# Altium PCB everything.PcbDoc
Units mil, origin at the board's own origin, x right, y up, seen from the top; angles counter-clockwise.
Board outline 6000 x 4000 mil, 2 copper layers (Top Layer, Bottom Layer); 0 components, 0 nets, 0 pads, 0 vias.
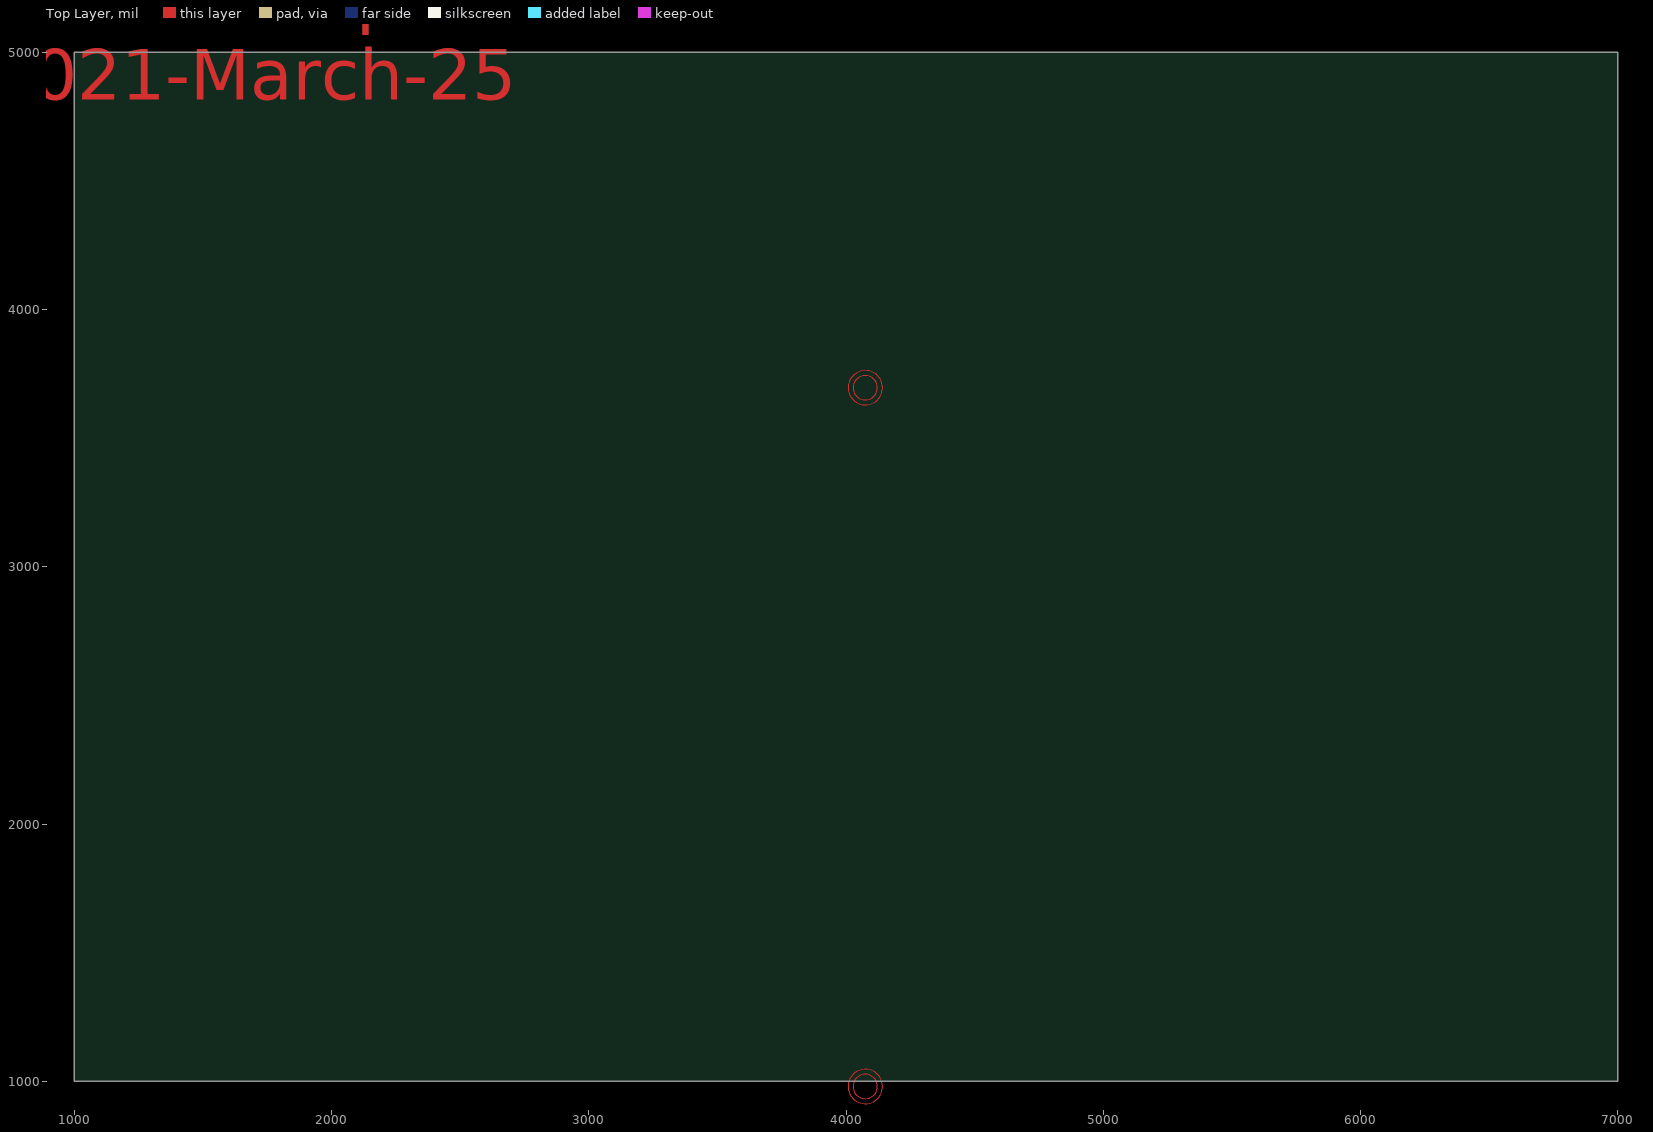
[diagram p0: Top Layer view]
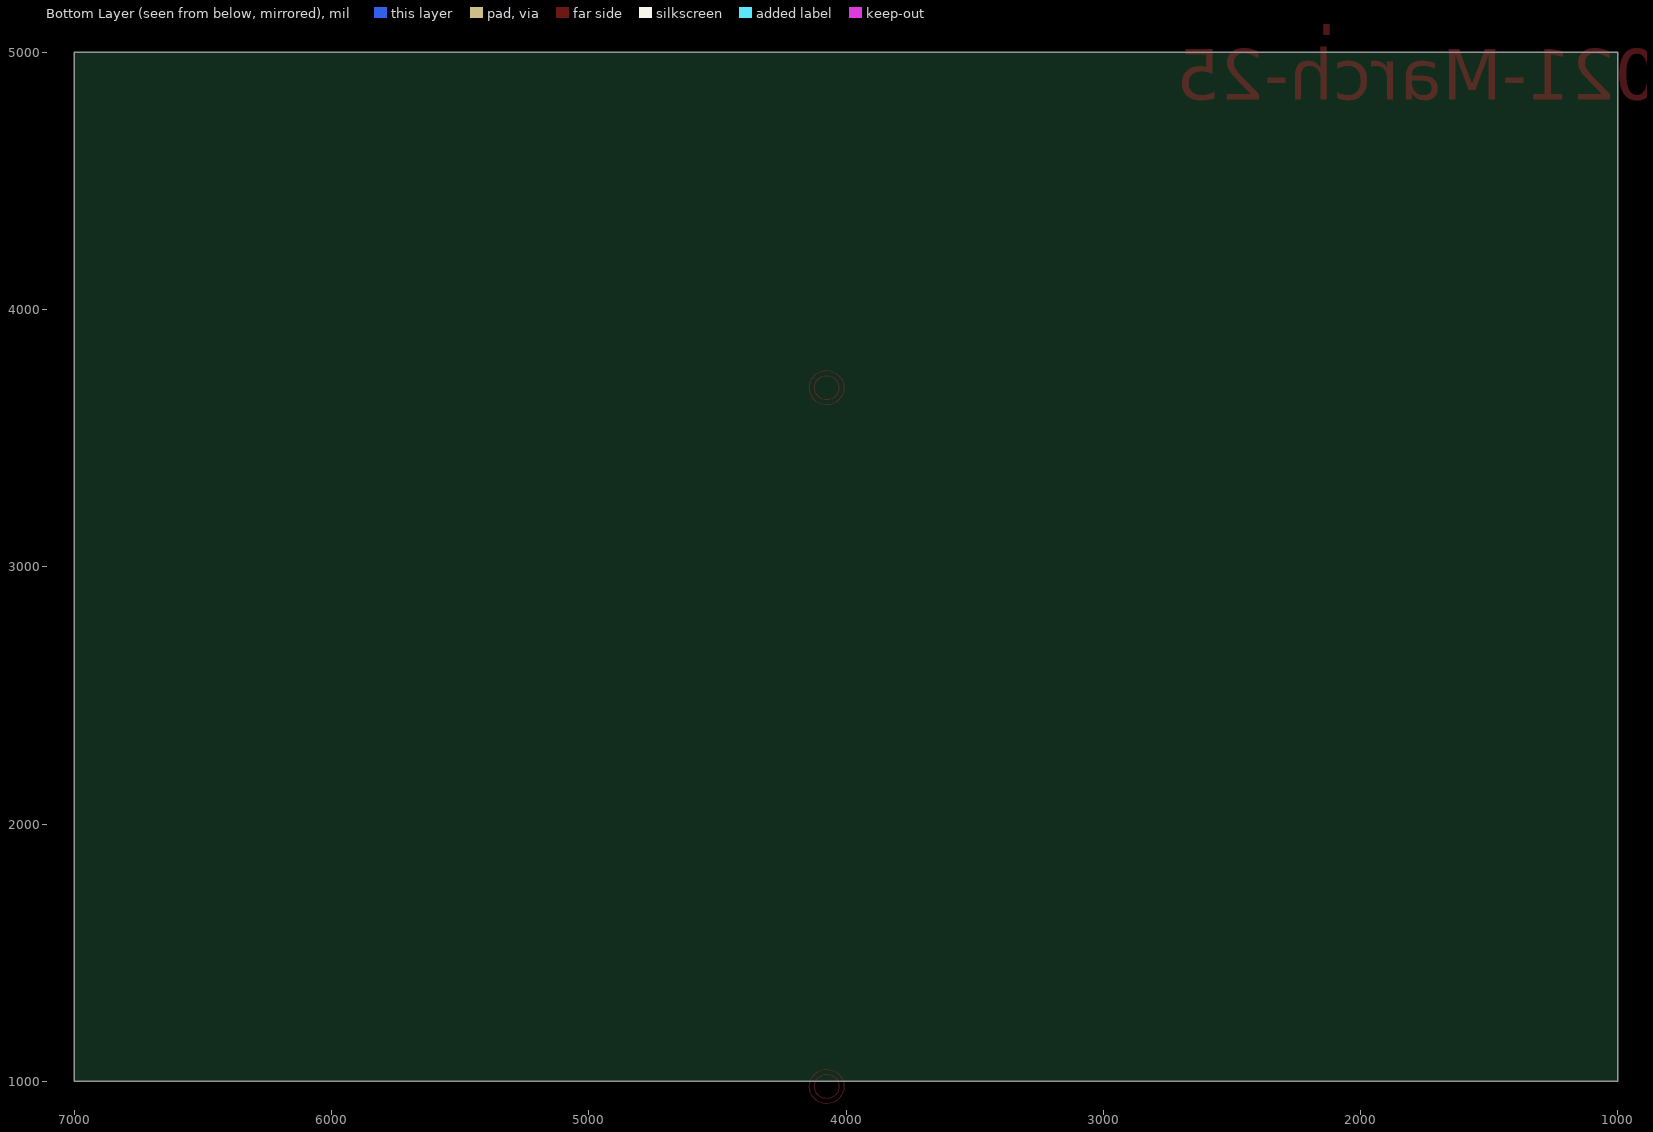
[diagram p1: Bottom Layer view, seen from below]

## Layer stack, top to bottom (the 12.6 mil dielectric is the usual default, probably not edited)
Top Solder: solder mask 0.4, Solder Resist, Dk 3.5
Top Layer: signal copper 1.4
Dielectric 1: dielectric 12.6, FR-4, Dk 4.8
Bottom Layer: signal copper 1.4
Bottom Solder: solder mask 0.4, Solder Resist, Dk 3.5

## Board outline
1000,1000 7000,1000 7000,5000 1000,5000

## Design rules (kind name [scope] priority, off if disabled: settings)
Clearance [All] p1: gap=10 ignorepadtopadclearanceinfootprint=FALSE except(0: Arc-Hole Track-Hole SMDPad-Hole THPad-Hole Via-Hole Fill-Hole Poly-Hole Region-Hole Text-Hole)
PolygonConnect [All] p1: connectstyle=Relief reliefconductorwidth=10 reliefentries=4 polygonreliefangle="90 Angle" airgapwidth=10
RoutingVias [All] p1: holewidth=28 width=50 viastyle="Through Hole" minholewidth=28 minwidth=50 maxholewidth=28 maxwidth=50
SolderMaskExpansion [All] p1: expansion=4 istentingtop=FALSE
Width [All] p1: maxlimit=10 minlimit=10 preferedwidth=10
30 further rules are at their usual default settings.

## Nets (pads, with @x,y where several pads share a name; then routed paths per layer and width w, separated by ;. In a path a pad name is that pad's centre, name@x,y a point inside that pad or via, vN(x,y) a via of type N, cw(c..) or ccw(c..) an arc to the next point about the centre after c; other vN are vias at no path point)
copper on no net: | length 46414.5
  Top Layer w0.5: 17253.01,7567.58 17253.01,7869.71 ; 17253.01,14476.48 17253.01,14778.6 ; 17351.43,7616.8 17941.98,7616.8 ; 17351.43,14525.69 17941.98,14525.69 ; 17573.21,7723.48 17589.66,7739.93 17622.43,7739.93 17638.88,7723.48 17638.88,7707.03 17622.43,7690.71 17589.66,7690.71 17573.21,7674.26 17573.21,7641.49 17638.88,7641.49 ; 17573.21,14632.37 17589.66,14648.83 17622.43,14648.83 17638.88,14632.37 17638.88,14615.92 17622.43,14599.6 17589.66,14599.6 17573.21,14583.15 17573.21,14550.38 17638.88,14550.38 ; 18040.41,7567.58 18040.41,7869.71 ; 18040.41,14476.48 18040.41,14778.6 ; 25456.33,7901.12 25456.33,8151.63 ; 25554.75,8102.42 25751.6,8102.42 ; 25596.22,8127.07 25628.97,8127.07 ; 25596.22,8209.05 25612.59,8225.51 25612.59,8127.07 ; 25850.03,7901.12 25850.03,8151.63 ; 26019.53,17666.21 26150.48,17666.21 ; 26019.53,18539.17 26085.01,18604.65 26215.95,18604.65 26281.42,18539.17 26281.42,18473.7 26215.95,18408.23 26085.01,18408.23 26019.53,18342.76 26019.53,18210.9 26281.42,18210.9 ; 26281.42,17468.88 26019.53,17468.88 26019.53,17862.62 26281.42,17862.62 ; 26675.17,17468.88 26609.7,17534.35 ; 26740.64,18539.17 26806.11,18604.65 26937.06,18604.65 27002.53,18539.17 27002.53,18473.7 26937.06,18408.23 26806.11,18408.23 26740.64,18342.76 26740.64,18210.9 27002.53,18210.9 ; 27068,17468.88 26871.59,17468.88 26806.11,17534.35 26806.11,17666.21 26871.59,17731.68 27068,17731.68 ; 27134.39,18210.9 27265.33,18210.9 ; 27134.39,18539.17 27199.86,18604.65 27199.86,18210.9 ; 27199.86,17468.88 27199.86,17862.62 ; 27199.86,17600.73 27330.8,17731.68 27396.28,17731.68 27461.75,17666.21 27461.75,17468.88 ; 27396.28,18408.23 27658.17,18408.23 ; 27790.02,18210.9 27790.02,18342.76 ; 27986.44,17468.88 28117.39,17468.88 ; 27986.44,17797.15 28051.91,17862.62 28051.91,17468.88 ; 28051.91,18210.9 28051.91,18342.76 ; 28182.86,18079.96 28182.86,18473.7 ; 28182.86,18210.9 28380.19,18210.9 28445.66,18276.37 28445.66,18408.23 28380.19,18473.7 28249.24,18473.7 28182.86,18408.23 ; 28576.6,17337.93 28576.6,17731.68 ; 28576.6,17468.88 28773.02,17468.88 28839.4,17534.35 28839.4,17666.21 28773.02,17731.68 28642.08,17731.68 28576.6,17666.21 ; 28576.6,18210.9 28576.6,18473.7 ; 28576.6,18342.76 28707.55,18473.7 28773.02,18473.7 28839.4,18408.23 ; 28970.35,18210.9 28970.35,18473.7 ; 28970.35,18539.17 28970.35,18604.65 ; 29101.29,18604.65 29101.29,18276.37 29166.77,18210.9 ; 29232.24,17468.88 29035.82,17468.88 28970.35,17534.35 28970.35,17666.21 29035.82,17731.68 29232.24,17731.68 ; 29297.71,18408.23 29560.51,18408.23 ; 29363.18,17468.88 29560.51,17468.88 29625.98,17534.35 29560.51,17600.73 29429.57,17600.73 29363.18,17666.21 29429.57,17731.68 29625.98,17731.68 ; 29691.46,18210.9 29822.4,18210.9 ; 29691.46,18539.17 29756.93,18604.65 29756.93,18210.9 ; 29953.35,18276.37 30019.73,18210.9 30150.67,18210.9 30216.15,18276.37 30216.15,18408.23 30150.67,18473.7 29953.35,18473.7 29953.35,18604.65 30216.15,18604.65 ; 26609.7,17534.35 26609.7,17666.21 26544.22,17731.68 26477.84,17731.68 26412.37,17666.21 26412.37,17534.35 26477.84,17468.88 26544.22,17468.88 26609.7,17534.35 ; 27790.02,18342.76 27920.97,18604.65 28051.91,18342.76 ; 27790.02,18342.76 28051.91,18342.76 ; 500.25,979.57 ccw(c453.01,979.57) 500.25,979.57 ; 500.25,7888.46 ccw(c453.01,7888.46) 500.25,7888.46 ; 500.25,10605 ccw(c453.01,10605) 500.25,10605 ; 519.93,979.57 ccw(c453.01,979.57) 519.93,979.57 ; 519.93,7888.46 ccw(c453.01,7888.46) 519.93,7888.46 ; 519.93,10605 ccw(c453.01,10605) 519.93,10605 ; 697.1,3696.11 ccw(c649.86,3696.11) 697.1,3696.11 ; 716.78,3696.11 ccw(c649.86,3696.11) 716.78,3696.11 ; 3925.45,10605 ccw(c3878.21,10605) 3925.45,10605 ; 3945.13,10605 ccw(c3878.21,10605) 3945.13,10605 ; 4122.3,979.57 ccw(c4075.06,979.57) 4122.3,979.57 ; 4122.3,3696.11 ccw(c4075.06,3696.11) 4122.3,3696.11 ; 4122.3,7888.46 ccw(c4075.06,7888.46) 4122.3,7888.46 ; 4141.98,979.57 ccw(c4075.06,979.57) 4141.98,979.57 ; 4141.98,3696.11 ccw(c4075.06,3696.11) 4141.98,3696.11 ; 4141.98,7888.46 ccw(c4075.06,7888.46) 4141.98,7888.46 ; 8887.55,886.08 ccw(c8840.3,886.08) 8887.55,886.08 ; 8887.55,3602.62 ccw(c8840.3,3602.62) 8887.55,3602.62 ; 8888.46,7794.97 ccw(c8841.21,7794.97) 8888.46,7794.97 ; 8907.23,886.08 ccw(c8840.3,886.08) 8907.23,886.08 ; 8907.23,3602.62 ccw(c8840.3,3602.62) 8907.23,3602.62 ; 8908.14,7794.97 ccw(c8841.21,7794.97) 8908.14,7794.97 ; 9282.16,10511.51 ccw(c9234.92,10511.51) 9282.16,10511.51 ; 9301.85,10511.51 ccw(c9234.92,10511.51) 9301.85,10511.51 ; 14478.1,3602.62 ccw(c14430.86,3602.62) 14478.1,3602.62 ; 14497.79,3602.62 ccw(c14430.86,3602.62) 14497.79,3602.62 ; 14871.8,886.08 ccw(c14824.56,886.08) 14871.8,886.08 ; 14872.71,7794.97 ccw(c14825.47,7794.97) 14872.71,7794.97 ; 14872.71,10511.51 ccw(c14825.47,10511.51) 14872.71,10511.51 ; 14891.49,886.08 ccw(c14824.56,886.08) 14891.49,886.08 ; 14892.4,7794.97 ccw(c14825.47,7794.97) 14892.4,7794.97 ; 14892.4,10511.51 ccw(c14825.47,10511.51) 14892.4,10511.51 ; 16742.92,961.76 ccw(c16695.67,961.76) 16742.92,961.76 ; 16742.92,4775.15 ccw(c16695.67,4775.15) 16742.92,4775.15 ; 16762.6,961.76 ccw(c16695.67,961.76) 16762.6,961.76 ; 16762.6,4775.15 ccw(c16695.67,4775.15) 16762.6,4775.15 ; 17319.93,7894.32 ccw(c17253.01,7894.32) 17319.93,7894.32 ; 17319.93,14803.21 ccw(c17253.01,14803.21) 17319.93,14803.21 ; 17671.65,7657.94 17687.97,7641.49 17704.42,7641.49 17720.87,7657.94 17720.87,7723.48 17704.42,7739.93 17687.97,7739.93 17671.65,7723.48 17671.65,7657.94 ; 17671.65,14566.83 17687.97,14550.38 17704.42,14550.38 17720.87,14566.83 17720.87,14632.37 17704.42,14648.83 17687.97,14648.83 17671.65,14632.37 17671.65,14566.83 ; 18087.65,7894.32 ccw(c18040.41,7894.32) 18087.65,7894.32 ; 18087.65,14803.21 ccw(c18040.41,14803.21) 18087.65,14803.21 ; 18087.65,17519.75 ccw(c18040.41,17519.75) 18087.65,17519.75 ; 18107.34,7894.32 ccw(c18040.41,7894.32) 18107.34,7894.32 ; 18107.34,14803.21 ccw(c18040.41,14803.21) 18107.34,14803.21 ; 18107.34,17519.75 ccw(c18040.41,17519.75) 18107.34,17519.75 ; 18284.5,10610.86 ccw(c18237.26,10610.86) 18284.5,10610.86 ; 18304.19,10610.86 ccw(c18237.26,10610.86) 18304.19,10610.86 ; 21058.05,843.65 ccw(c21010.8,843.65) 21058.05,843.65 ; 21058.05,4775.15 ccw(c21010.8,4775.15) 21058.05,4775.15 ; 21077.73,843.65 ccw(c21010.8,843.65) 21077.73,843.65 ; 21077.73,4775.15 ccw(c21010.8,4775.15) 21077.73,4775.15 ; 21512.85,17519.75 ccw(c21465.61,17519.75) 21512.85,17519.75 ; 21532.54,17519.75 ccw(c21465.61,17519.75) 21532.54,17519.75 ; 21709.7,7894.32 ccw(c21662.46,7894.32) 21709.7,7894.32 ; 21709.7,10610.86 ccw(c21662.46,10610.86) 21709.7,10610.86 ; 21709.7,14803.21 ccw(c21662.46,14803.21) 21709.7,14803.21 ; 21729.39,7894.32 ccw(c21662.46,7894.32) 21729.39,7894.32 ; 21729.39,10610.86 ccw(c21662.46,10610.86) 21729.39,10610.86 ; 21729.39,14803.21 ccw(c21662.46,14803.21) 21729.39,14803.21 ; 25523.26,7876.51 ccw(c25456.33,7876.51) 25523.26,7876.51 ; 25661.73,8143.45 25678.19,8127.07 25694.57,8127.07 25710.95,8143.45 25710.95,8209.05 25694.57,8225.51 25678.19,8225.51 25661.73,8209.05 25661.73,8143.45 ; 25897.27,7876.51 ccw(c25850.03,7876.51) 25897.27,7876.51 ; 25897.27,11689.9 ccw(c25850.03,11689.9) 25897.27,11689.9 ; 25916.96,7876.51 ccw(c25850.03,7876.51) 25916.96,7876.51 ; 25916.96,11689.9 ccw(c25850.03,11689.9) 25916.96,11689.9 ; 26412.37,18276.37 26477.84,18210.9 26544.22,18210.9 26609.7,18276.37 26609.7,18539.17 26544.22,18604.65 26477.84,18604.65 26412.37,18539.17 26412.37,18276.37 ; 28249.24,17534.35 28314.71,17468.88 28380.19,17468.88 28445.66,17534.35 28445.66,17797.15 28380.19,17862.62 28314.71,17862.62 28249.24,17797.15 28249.24,17534.35 ; 30212.4,7758.4 ccw(c30165.16,7758.4) 30212.4,7758.4 ; 30212.4,11689.9 ccw(c30165.16,11689.9) 30212.4,11689.9 ; 30232.09,7758.4 ccw(c30165.16,7758.4) 30232.09,7758.4 ; 30232.09,11689.9 ccw(c30165.16,11689.9) 30232.09,11689.9

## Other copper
Top Layer:
  region: 17253.01,7974.7 17180.83,8132.18 17325.18,8132.18
  region: 17351.43,7600.39 17253.01,7616.8 17351.43,7633.2
  region: 18040.41,7616.8 17941.98,7600.39 17941.98,7633.2
  region: 17253.01,14883.59 17180.83,15041.07 17325.18,15041.07
  region: 17351.43,14509.28 17253.01,14525.69 17351.43,14542.09
  region: 18040.41,14525.69 17941.98,14509.28 17941.98,14542.09
  region: 25528.5,7638.65 25384.15,7638.65 25456.33,7796.13
  region: 25554.75,8086.01 25456.33,8102.42 25554.75,8118.82
  region: 25850.03,8102.42 25751.6,8086.01 25751.6,8118.82
  region: 8913.39,648.22 8769.04,648.22 8841.21,805.7
  region: 8913.39,7557.11 8769.04,7557.11 8841.21,7714.59
  region: 16767.85,723.9 16623.5,723.9 16695.67,881.38
  region: 525.18,741.71 380.83,741.71 453.01,899.19
  region: 525.18,7650.6 380.83,7650.6 453.01,7808.08
  text "2G4 RX Bottom" at 17467.73,18948.66 h196.85
  text "2021-April-15" at 17467.73,18639.1 h196.85
  text "2.0mm Thickness board" at 26021.54,17036.26 h196.85
  text "2G4 RX Top" at 17467.73,12039.77 h196.85
  text "2G4 RX Bottom" at 667.73,12033.91 h196.85
  text "Tracer Top" at 9157.41,12033.91 h196.85
  text "2021-April-15" at 17467.73,11730.21 h196.85
  text "2021-March-25" at 667.73,11724.35 h196.85
  text "2021-March-25" at 9157.41,11724.35 h196.85
  text "2021-March-25" at 30971.01,10705.11 h196.85 r270
  text "Micro TX" at 31280.57,10705.11 h196.85 r270
  text "2.0mm thickness board" at 10299.46,6160.38 h196.85
  text "2G4 RX Top" at 667.73,5125.02 h196.85
  text "Tracer Bottom" at 9157.41,5125.02 h196.85
  text "2021-March-25" at 667.73,4815.46 h196.85
  text "2021-March-25" at 9157.41,4815.46 h196.85
  text "Micro TX" at 21161.59,2942.44 h196.85
  text "2021-March-25" at 21161.59,2632.88 h196.85

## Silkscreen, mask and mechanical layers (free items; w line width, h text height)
Mechanical 3:
  drawing of 768 lines, arcs and shapes, not listed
